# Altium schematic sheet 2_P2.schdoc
size 307 x 218 mm; Symbol: Drawing-Symbol_A4; Device: Drawing-Symbol_A4; @Project Name: ESP32 Drone; @Page Count: 2; @Update Date: 2026-03-31; @Create Date: 2026-03-29; @Schematic Name: Schematic1; @Page No: 2; @Page Name: P2; Company: Sprig Labs; Version: V1.0; Page Size: A4; Drawn: K. Paraskevas; @Create Time: 20:04:18; @Update Time: 17:41:14; Width: 1170; Height: 825; Region Start: 1; X Region Count: 6; Y Region Count: 4; Blade Width: 10; Title Block Position: 3; @Board Name: Board1
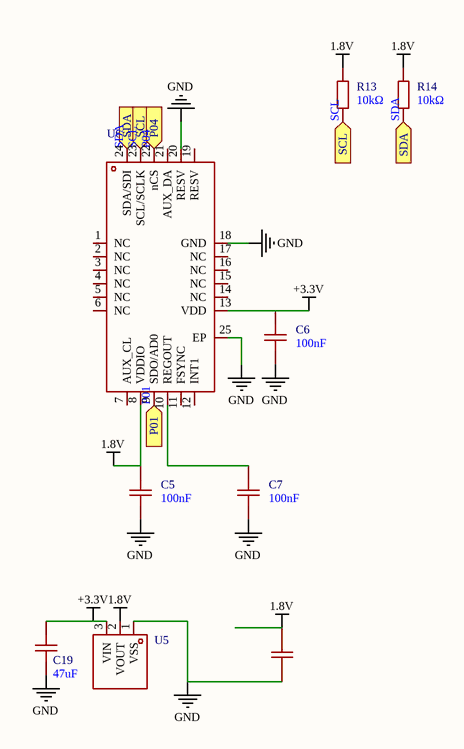
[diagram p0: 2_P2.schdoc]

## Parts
C5  100nF  [C0603]
C6  100nF  [C0603]
C7  100nF  [C0603]
C17  47uF  [C0805]  (value not drawn)
C19  47uF  [C0805]
R13  10kΩ  [R0603]
R14  10kΩ  [R0603]
U5  XC6206P182MR  [SOT-23-3_L2.9-W1.6-P1.90-LS2.8-BR]  (value not drawn)
U6  ICM-20948  [QFN-24_L3.0-W3.0-P0.40-BL-EP]  (value not drawn)

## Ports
P01 (in), P04 (in), SCL (in), SDA (in)

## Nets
1.8V: C5.2 C17.2 R13.2 R14.2 U5.2(VOUT) U6.8(VDDIO)
+3.3V: C6.2 C19.2 U5.3(VIN) U6.13(VDD)
GND: C5.1 C6.1 C7.1 C17.1 C19.1 U5.1(VSS) U6.18(GND) U6.20(RESV) U6.25(EP)
P01: U6.9(SDO/AD0) ; port P01
P04: U6.22(nCS) ; port P04
SCL: R13.1 U6.23(SCL/SCLK) ; port SCL
SDA: R14.1 U6.24(SDA/SDI) ; port SDA
NetC7_2: C7.2 U6.10(REGOUT)

Not connected (* = marked no-connect by the designer): U6 1(NC) 2(NC) 3(NC) 4(NC) 5(NC) 6(NC) 7(AUX_CL) 11(FSYNC) 12(INT1) 14(NC) 15(NC) 16(NC) 17(NC) 19(RESV) 21(AUX_DA)

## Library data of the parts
C5-C7 = CC0603KRX7R9BB104: Manufacturer: YAGEO(国巨); Add into BOM: yes; Tolerance: ±10%; Voltage Rating: 50V; Temperature Coefficient: X7R
C17 C19 = JMK212BJ476MG-T: Manufacturer: TAIYO YUDEN(太诱); Symbol: TCC0603X5R226M6R3CT; Add into BOM: yes; Tolerance: ±20%; Voltage Rating: 6.3V; Temperature Coefficient: X5R
R13 R14 = 0603WAF1002T5E: Manufacturer: UNI-ROYAL(厚声); Symbol: 0603WAF1003T5E; Add into BOM: yes; Tolerance: ±1%; Power(Watts): 100mW; Voltage-Supply(Max): 75V; Temperature Coefficient: ±100ppm/℃
U5 = XC6206P182MR_C22466430: Manufacturer: TDSEMIC(拓电半导体); Add into BOM: yes; Output Type: Fixed; Maximum Input Voltage: 6.5V; Output Voltage: 1.8V; Output Polarity: Positive electrode; Number of Outputs: 1
U6 = ICM-20948: Manufacturer: TDK InvenSense(应美盛); Add into BOM: yes; Accelerometer Sensing Axis: X,Y,Z; Acceleration Measurement Range (MAX): ±16g; Gyroscope Measurement Range (MAX): ±2000dps; Sensor Type: Accelerometer Gyroscope; Output Bits: 16bit; Interface: I2C；SPI; Voltage - Supply: 1.71V~3.6V; Cache Size: 0.5KB; Standby Current: 8uA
